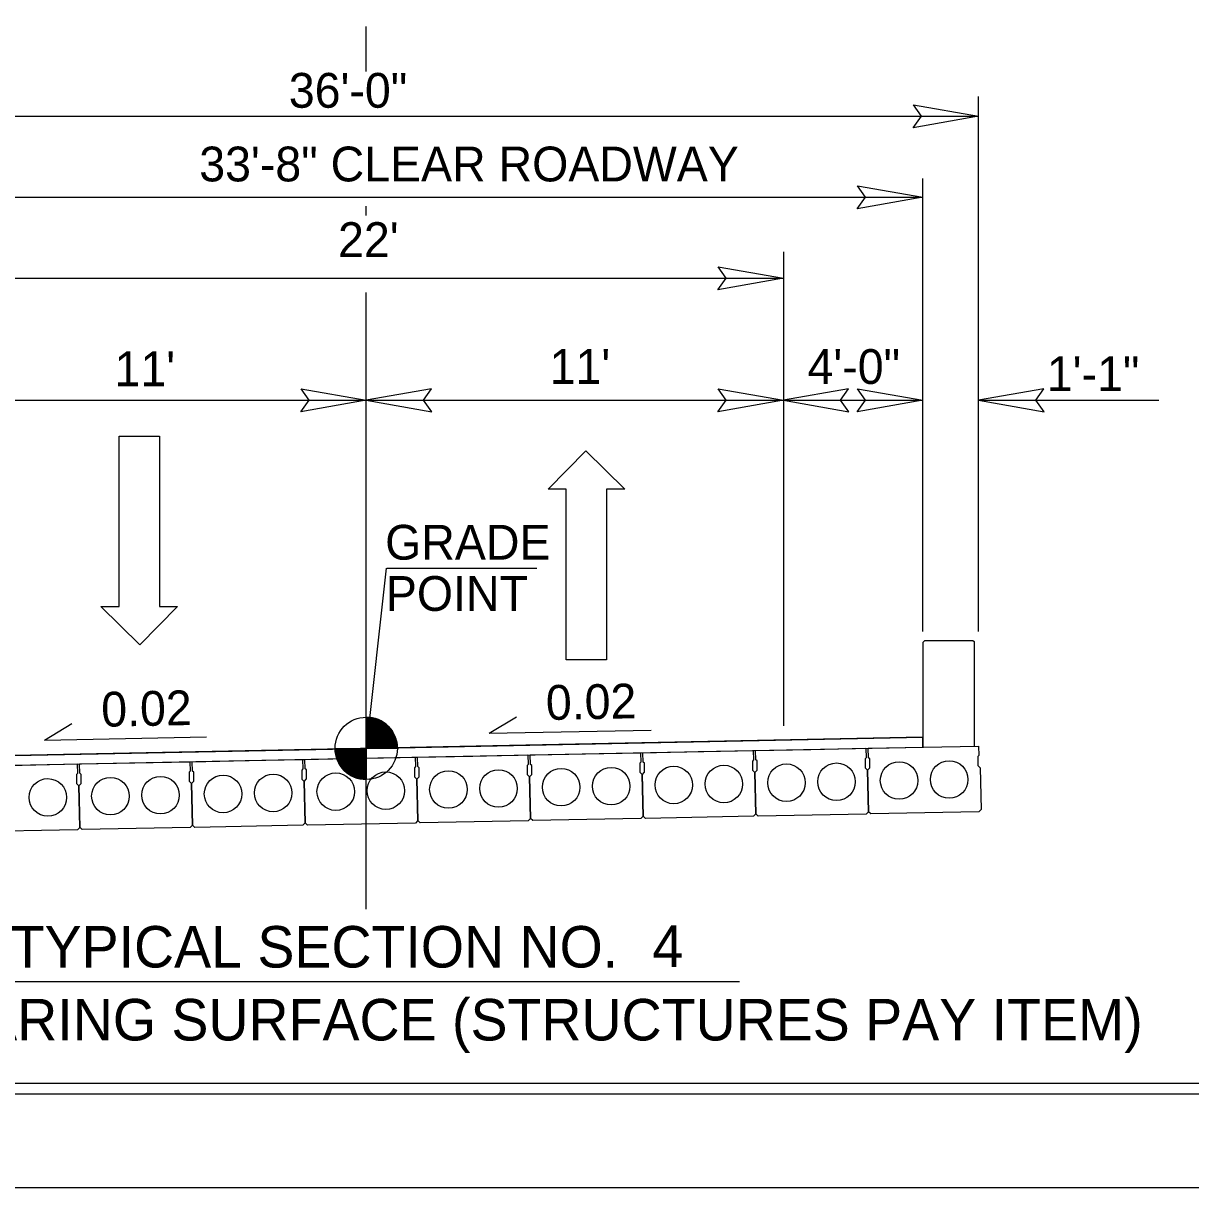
# Model space of a CAD drawing. Extents: x 573732 to 574187, y -53389 to -53257.
# Drawn here: x 573847.31 to 573880.88, y -53388.95 to -53355.48 of the extents above; entities that cross this region are included whole.
import ezdxf

# ---------------------------------------------------------------- set-up
doc = ezdxf.new("R2010")
doc.units = 0
for name, color, linetype in [('Old_Level_60', 7, 'Continuous'), ('Prop Dimension', 7, 'Continuous'), ('Prop Lane Arrow CELL', 7, 'Continuous'), ('Prop Shade Light', 7, 'Continuous'), ('Sheet Cutting Line CELL', 7, 'Continuous'), ('Sheet Plot Border Inside CELL', 7, 'Continuous'), ('Sheet Plot Border Outside CELL', 7, 'Continuous'), ('Sheet Typical CELL', 7, 'Continuous'), ('Typical Bridge Rail CELL', 7, 'Continuous'), ('Typical Grade Point Symbol CELL', 7, 'Continuous'), ('Typical Pavement Slope CELL', 7, 'Continuous'), ('Typical Pavement Slope Information CELL', 7, 'Continuous'), ('Typical Terminator CELL', 7, 'Continuous'), ('Typical Text Centerline CELL', 7, 'Continuous'), ('Typical Text Grade Point CELL', 7, 'Continuous'), ('Typical Text Label CELL', 7, 'Continuous')]:
    doc.layers.add(name, color=color, linetype=linetype)

msp = doc.modelspace()

# ---------------------------------------------------------------- linework, layer by layer
at = {"layer": 'Old_Level_60'}
for points in [[(573861.887, -53376.511), (573863.475, -53376.48), (573865.061, -53376.448), (573865.067, -53376.719), (573865.034, -53376.752), (573865.039, -53377.011), (573865.107, -53377.077), (573865.131, -53378.271), (573865.065, -53378.339), (573861.96, -53378.4), (573861.891, -53378.334), (573861.867, -53377.143), (573861.934, -53377.074), (573861.928, -53376.813), (573861.893, -53376.782), (573861.887, -53376.511)], [(573865.127, -53376.448), (573866.715, -53376.417), (573868.301, -53376.384), (573868.307, -53376.655), (573868.274, -53376.689), (573868.279, -53376.948), (573868.347, -53377.014), (573868.371, -53378.208), (573868.305, -53378.276), (573865.2, -53378.337), (573865.131, -53378.271), (573865.107, -53377.079), (573865.174, -53377.01), (573865.168, -53376.75), (573865.133, -53376.719), (573865.127, -53376.448)], [(573868.368, -53376.383), (573869.955, -53376.352), (573871.541, -53376.319), (573871.547, -53376.59), (573871.514, -53376.623), (573871.519, -53376.883), (573871.588, -53376.949), (573871.611, -53378.142), (573871.546, -53378.211), (573868.44, -53378.271), (573868.371, -53378.206), (573868.347, -53377.014), (573868.414, -53376.945), (573868.408, -53376.685), (573868.374, -53376.653), (573868.368, -53376.383)], [(573871.608, -53376.319), (573873.195, -53376.288), (573874.781, -53376.256), (573874.787, -53376.527), (573874.754, -53376.56), (573874.759, -53376.819), (573874.827, -53376.886), (573874.851, -53378.079), (573874.786, -53378.147), (573871.68, -53378.208), (573871.611, -53378.142), (573871.587, -53376.951), (573871.654, -53376.882), (573871.648, -53376.621), (573871.614, -53376.59), (573871.608, -53376.319)], [(573845.686, -53376.834), (573847.274, -53376.802), (573848.86, -53376.77), (573848.866, -53377.041), (573848.833, -53377.074), (573848.838, -53377.334), (573848.906, -53377.4), (573848.93, -53378.593), (573848.864, -53378.662), (573845.759, -53378.722), (573845.69, -53378.657), (573845.666, -53377.465), (573845.733, -53377.396), (573845.727, -53377.135), (573845.692, -53377.104), (573845.686, -53376.834)], [(573848.927, -53376.768), (573850.514, -53376.737), (573852.1, -53376.705), (573852.106, -53376.976), (573852.073, -53377.009), (573852.078, -53377.268), (573852.146, -53377.335), (573852.17, -53378.528), (573852.105, -53378.597), (573848.999, -53378.657), (573848.93, -53378.591), (573848.906, -53377.4), (573848.973, -53377.331), (573848.967, -53377.07), (573848.933, -53377.039), (573848.927, -53376.768)], [(573852.167, -53376.705), (573853.754, -53376.674), (573855.34, -53376.642), (573855.346, -53376.912), (573855.313, -53376.946), (573855.318, -53377.205), (573855.386, -53377.271), (573855.41, -53378.465), (573855.345, -53378.533), (573852.239, -53378.594), (573852.17, -53378.528), (573852.146, -53377.336), (573852.213, -53377.267), (573852.207, -53377.007), (573852.173, -53376.976), (573852.167, -53376.705)], [(573855.407, -53376.64), (573856.995, -53376.609), (573858.581, -53376.576), (573858.586, -53376.847), (573858.554, -53376.881), (573858.558, -53377.14), (573858.627, -53377.206), (573858.65, -53378.399), (573858.585, -53378.468), (573855.48, -53378.528), (573855.41, -53378.463), (573855.386, -53377.271), (573855.454, -53377.202), (573855.448, -53376.942), (573855.413, -53376.911), (573855.407, -53376.64)], [(573858.647, -53376.576), (573860.235, -53376.545), (573861.82, -53376.513), (573861.826, -53376.784), (573861.794, -53376.817), (573861.798, -53377.076), (573861.867, -53377.143), (573861.89, -53378.336), (573861.825, -53378.405), (573858.72, -53378.465), (573858.65, -53378.399), (573858.626, -53377.208), (573858.694, -53377.139), (573858.688, -53376.878), (573858.653, -53376.847), (573858.647, -53376.576)]]:
    msp.add_lwpolyline(points, dxfattribs=at)
for centre in [(573866.014, -53377.375), (573867.454, -53377.347), (573869.254, -53377.31), (573870.694, -53377.282), (573872.494, -53377.247), (573873.934, -53377.218), (573849.813, -53377.696), (573851.253, -53377.667), (573853.053, -53377.633), (573854.493, -53377.604), (573856.293, -53377.567), (573857.733, -53377.539), (573859.533, -53377.504), (573860.973, -53377.475), (573862.774, -53377.439), (573864.214, -53377.41), (573848.013, -53377.732)]:
    msp.add_ellipse(centre, major_axis=(0.001, 0.54), ratio=0.999904, dxfattribs=at)
at = {"layer": 'Prop Dimension'}
for p, q in [((573874.781, -53372.964), (573874.781, -53357.591)), ((573835.945, -53358.149), (573874.781, -53358.149)), ((573873.174, -53372.964), (573873.174, -53359.942)), ((573837.514, -53360.479), (573873.174, -53360.479)), ((573869.175, -53375.673), (573869.175, -53362.052)), ((573845.206, -53362.808), (573869.166, -53362.808)), ((573845.138, -53366.315), (573857.171, -53366.315)), ((573857.171, -53366.315), (573869.166, -53366.315)), ((573869.166, -53366.315), (573873.174, -53366.315)), ((573874.781, -53366.315), (573879.963, -53366.315)), ((573857.747, -53371.145), (573857.171, -53376.322)), ((573857.757, -53371.145), (573862.077, -53371.145))]:
    msp.add_line(p, q, dxfattribs=at)
at = {"layer": 'Prop Lane Arrow CELL'}
for p, q in [((573850.066, -53372.245), (573850.066, -53367.345)), ((573850.066, -53367.345), (573851.221, -53367.345)), ((573851.221, -53367.345), (573851.221, -53372.245)), ((573862.397, -53368.874), (573863.482, -53367.772)), ((573863.482, -53367.772), (573864.602, -53368.874)), ((573862.922, -53368.874), (573862.397, -53368.874)), ((573862.922, -53373.774), (573862.922, -53368.874)), ((573864.602, -53368.874), (573864.077, -53368.874)), ((573864.077, -53368.874), (573864.077, -53373.774)), ((573850.661, -53373.348), (573849.541, -53372.245)), ((573849.541, -53372.245), (573850.066, -53372.245)), ((573851.746, -53372.245), (573850.661, -53373.348)), ((573851.221, -53372.245), (573851.746, -53372.245)), ((573864.077, -53373.774), (573862.922, -53373.774))]:
    msp.add_line(p, q, dxfattribs=at)
at = {"layer": 'Prop Shade Light'}
for p, q in [((573873.174, -53376.002), (573857.004, -53376.325)), ((573873.174, -53376.285), (573873.174, -53376.002)), ((573857.004, -53376.325), (573837.514, -53376.715)), ((573857.01, -53376.608), (573873.174, -53376.285)), ((573837.519, -53376.998), (573857.01, -53376.608)), ((573855.34, -53376.642), (573855.407, -53376.64))]:
    msp.add_line(p, q, dxfattribs=at)
at = {"layer": 'Sheet Cutting Line CELL'}
msp.add_line((573782.222, -53388.948), (573984.302, -53388.948), dxfattribs=at)
at = {"layer": 'Sheet Plot Border Inside CELL'}
msp.add_lwpolyline([(573983.762, -53259.642), (573783.782, -53259.642), (573783.782, -53386.254), (573983.762, -53386.254)], close=True, dxfattribs=at)
at = {"layer": 'Sheet Plot Border Outside CELL'}
msp.add_lwpolyline([(573984.302, -53256.948), (573782.222, -53256.948), (573782.222, -53388.948), (573984.302, -53388.948)], close=True, dxfattribs=at)
at = {"layer": 'Sheet Typical CELL'}
msp.add_lwpolyline([(573982.262, -53259.948), (573802.262, -53259.948), (573802.262, -53385.948), (573982.262, -53385.948)], close=True, dxfattribs=at)
at = {"layer": 'Typical Bridge Rail CELL'}
for p, q in [((573873.236, -53373.221), (573873.174, -53373.284)), ((573873.174, -53373.284), (573873.174, -53376.289)), ((573873.236, -53373.221), (573874.618, -53373.221)), ((573874.618, -53373.221), (573874.651, -53373.254)), ((573874.651, -53373.254), (573874.651, -53376.258))]:
    msp.add_line(p, q, dxfattribs=at)
at = {"layer": 'Typical Grade Point Symbol CELL'}
for p, q in [((573857.171, -53376.322), (573857.171, -53375.427)), ((573856.275, -53376.322), (573857.171, -53376.322)), ((573857.169, -53377.217), (573857.171, -53376.322)), ((573857.171, -53376.322), (573857.169, -53377.217)), ((573858.066, -53376.322), (573857.171, -53376.322))]:
    msp.add_line(p, q, dxfattribs=at)
for points in [[(573857.179, -53375.427), (573857.179, -53375.427), (573857.179, -53376.322)], [(573857.196, -53375.427), (573857.196, -53376.322)], [(573857.214, -53375.429), (573857.214, -53376.322)], [(573857.232, -53375.429), (573857.232, -53376.322)], [(573857.25, -53375.431), (573857.25, -53376.322)], [(573857.268, -53375.433), (573857.268, -53376.322)], [(573857.286, -53375.435), (573857.286, -53376.322)], [(573857.304, -53375.437), (573857.304, -53376.322)], [(573857.322, -53375.439), (573857.322, -53376.322)], [(573857.34, -53375.443), (573857.34, -53376.322)], [(573857.358, -53375.447), (573857.358, -53376.322)], [(573857.376, -53375.451), (573857.376, -53376.322)], [(573857.393, -53375.455), (573857.393, -53376.322)], [(573857.411, -53375.46), (573857.411, -53376.322)], [(573857.429, -53375.465), (573857.429, -53376.322)], [(573857.447, -53375.47), (573857.447, -53376.322)], [(573857.465, -53375.476), (573857.465, -53376.322)], [(573857.483, -53375.482), (573857.483, -53376.322)], [(573857.501, -53375.49), (573857.501, -53376.322)], [(573857.519, -53375.498), (573857.519, -53376.322)], [(573857.537, -53375.506), (573857.537, -53376.322)], [(573857.555, -53375.514), (573857.555, -53376.322)], [(573857.572, -53375.522), (573857.572, -53376.322)], [(573857.59, -53375.532), (573857.59, -53376.322)], [(573857.608, -53375.542), (573857.608, -53376.322)], [(573857.626, -53375.552), (573857.626, -53376.322)], [(573857.644, -53375.562), (573857.644, -53376.322)], [(573857.662, -53375.574), (573857.662, -53376.322)], [(573857.68, -53375.586), (573857.68, -53376.322)], [(573857.698, -53375.6), (573857.698, -53376.322)], [(573857.716, -53375.612), (573857.716, -53376.322)], [(573857.734, -53375.626), (573857.734, -53376.322)], [(573857.751, -53375.641), (573857.751, -53376.322)], [(573857.769, -53375.657), (573857.769, -53376.322)], [(573857.787, -53375.673), (573857.787, -53376.322)], [(573857.805, -53375.691), (573857.805, -53376.322)], [(573857.823, -53375.709), (573857.823, -53376.322)], [(573857.841, -53375.729), (573857.841, -53376.322)], [(573857.859, -53375.751), (573857.859, -53376.322)], [(573857.877, -53375.773), (573857.877, -53376.322)], [(573857.895, -53375.797), (573857.895, -53376.322)], [(573857.913, -53375.823), (573857.913, -53376.322)], [(573857.931, -53375.85), (573857.931, -53376.322)], [(573857.948, -53375.88), (573857.948, -53376.322)], [(573857.966, -53375.912), (573857.966, -53376.322)], [(573857.984, -53375.95), (573857.984, -53376.322)], [(573858.002, -53375.992), (573858.002, -53376.322)], [(573858.02, -53376.041), (573858.02, -53376.322)], [(573858.038, -53376.103), (573858.038, -53376.322)], [(573856.279, -53376.322), (573856.279, -53376.419)], [(573856.297, -53376.322), (573856.297, -53376.525)], [(573856.315, -53376.322), (573856.315, -53376.588)], [(573856.333, -53376.322), (573856.333, -53376.642)], [(573856.351, -53376.322), (573856.351, -53376.684)], [(573856.369, -53376.322), (573856.369, -53376.722)], [(573856.387, -53376.322), (573856.387, -53376.755)], [(573856.405, -53376.322), (573856.405, -53376.787)], [(573856.423, -53376.322), (573856.423, -53376.815)], [(573856.441, -53376.322), (573856.441, -53376.841)], [(573856.458, -53376.322), (573856.458, -53376.865)], [(573856.476, -53376.322), (573856.476, -53376.887)], [(573856.494, -53376.322), (573856.494, -53376.909)], [(573856.512, -53376.322), (573856.512, -53376.929)], [(573856.53, -53376.322), (573856.53, -53376.948)], [(573856.548, -53376.322), (573856.548, -53376.966)], [(573856.566, -53376.322), (573856.566, -53376.982)], [(573856.584, -53376.322), (573856.584, -53376.998)], [(573856.602, -53376.322), (573856.602, -53377.014)], [(573856.62, -53376.322), (573856.62, -53377.028)], [(573856.638, -53376.322), (573856.638, -53377.042)], [(573856.655, -53376.322), (573856.655, -53377.054)], [(573856.673, -53376.322), (573856.673, -53377.066)], [(573856.691, -53376.322), (573856.691, -53377.078)], [(573856.709, -53376.322), (573856.709, -53377.09)], [(573856.727, -53376.322), (573856.727, -53377.1)], [(573856.745, -53376.322), (573856.745, -53377.11)], [(573856.763, -53376.322), (573856.763, -53377.12)], [(573856.781, -53376.322), (573856.781, -53377.128)], [(573856.799, -53376.322), (573856.799, -53377.136)], [(573856.817, -53376.322), (573856.817, -53377.143)], [(573856.834, -53376.322), (573856.834, -53377.151)], [(573856.852, -53376.322), (573856.852, -53377.159)], [(573856.87, -53376.322), (573856.87, -53377.165)], [(573856.888, -53376.322), (573856.888, -53377.171)], [(573856.906, -53376.322), (573856.906, -53377.177)], [(573856.924, -53376.322), (573856.924, -53377.181)], [(573856.942, -53376.322), (573856.942, -53377.187)], [(573856.96, -53376.322), (573856.96, -53377.191)], [(573856.978, -53376.322), (573856.978, -53377.195)], [(573856.996, -53376.322), (573856.996, -53377.199)], [(573857.013, -53376.322), (573857.013, -53377.203)], [(573857.031, -53376.322), (573857.031, -53377.205)], [(573857.049, -53376.322), (573857.049, -53377.209)], [(573857.067, -53376.322), (573857.067, -53377.211)], [(573857.085, -53376.322), (573857.085, -53377.213)], [(573857.103, -53376.322), (573857.103, -53377.215)], [(573857.121, -53376.322), (573857.121, -53377.215)], [(573857.139, -53376.322), (573857.139, -53377.217)], [(573857.157, -53376.322), (573857.157, -53377.217), (573857.157, -53377.217)], [(573858.056, -53376.195), (573858.056, -53376.322)]]:
    msp.add_lwpolyline(points, dxfattribs=at)
msp.add_circle((573857.17, -53376.322), 0.895, dxfattribs=at)
for start, end in [(359.9905, 89.9905), (179.9905, 269.9905)]:
    msp.add_arc((573857.17, -53376.322), 0.895, start, end, dxfattribs=at)
at = {"layer": 'Typical Pavement Slope CELL'}
for p, q in [((573857.171, -53376.322), (573873.174, -53376.002)), ((573873.174, -53376.002), (573873.174, -53376.285)), ((573837.514, -53376.715), (573857.171, -53376.322)), ((573857.176, -53376.605), (573873.174, -53376.285)), ((573837.514, -53376.995), (573857.176, -53376.605))]:
    msp.add_line(p, q, dxfattribs=at)
at = {"layer": 'Typical Pavement Slope Information CELL'}
for p, q in [((573860.704, -53375.89), (573861.487, -53375.417)), ((573847.917, -53376.085), (573848.7, -53375.612)), ((573860.704, -53375.89), (573865.364, -53375.797)), ((573847.917, -53376.085), (573852.578, -53375.992))]:
    msp.add_line(p, q, dxfattribs=at)
at = {"layer": 'Typical Terminator CELL'}
for points in [[(573872.906, -53357.827), (573874.781, -53358.149), (573872.896, -53358.483), (573873.136, -53358.149)], [(573871.299, -53360.156), (573873.174, -53360.479), (573871.288, -53360.812), (573871.528, -53360.479)], [(573867.292, -53362.485), (573869.166, -53362.808), (573867.281, -53363.141), (573867.521, -53362.808)], [(573855.296, -53365.992), (573857.171, -53366.315), (573855.285, -53366.648), (573855.525, -53366.315)], [(573859.045, -53365.992), (573857.171, -53366.315), (573859.056, -53366.648), (573858.816, -53366.315)], [(573867.292, -53365.992), (573869.166, -53366.315), (573867.281, -53366.648), (573867.521, -53366.315)], [(573871.041, -53365.992), (573869.166, -53366.315), (573871.051, -53366.648), (573870.812, -53366.315)], [(573871.299, -53365.992), (573873.174, -53366.315), (573871.288, -53366.648), (573871.528, -53366.315)], [(573876.656, -53365.992), (573874.781, -53366.315), (573876.666, -53366.648), (573876.427, -53366.315)]]:
    msp.add_lwpolyline(points, close=True, dxfattribs=at)
at = {"layer": 'Typical Text Centerline CELL'}
for p, q in [((573857.171, -53356.866), (573857.171, -53355.571)), ((573857.171, -53361.006), (573857.171, -53360.742)), ((573857.171, -53380.943), (573857.171, -53363.221))]:
    msp.add_line(p, q, dxfattribs=at)
at = {"layer": 'Typical Text Label CELL'}
msp.add_line((573846.304, -53383.022), (573867.908, -53383.022), dxfattribs=at)

# ---------------------------------------------------------------- texts
at = {"layer": 'Typical Pavement Slope Information CELL'}
for s, rotation, p in [('36\'-0"', 360, (573854.943, -53357.91)), ("22'", 360, (573856.359, -53362.2)), ("11'", 360, (573849.93, -53365.914)), ("11'", 360, (573862.444, -53365.846)), ('4\'-0"', 360, (573869.86, -53365.848)), ('0.02', 1.1457, (573862.345, -53375.508)), ('0.02', 1.1457, (573849.558, -53375.703))]:
    msp.add_text(s, height=1, rotation=rotation, dxfattribs=at).set_placement(p)
for s, p in [('33\'-8" CLEAR ROADWAY', (573852.367, -53360.027)), ('1\'-1"', (573876.742, -53366.055))]:
    msp.add_text(s, height=1, dxfattribs=at).set_placement(p)
at = {"layer": 'Typical Text Grade Point CELL'}
for s, p in [('GRADE', (573857.713, -53370.899)), ('POINT', (573857.734, -53372.371))]:
    msp.add_text(s, height=1, dxfattribs=at).set_placement(p)
at = {"layer": 'Typical Text Label CELL'}
for s, height, p in [('TYPICAL SECTION NO.  ', 1.19356, (573846.944, -53382.622)), ('4', 1.194, (573865.397, -53382.606))]:
    msp.add_text(s, height=height, rotation=360, dxfattribs=at).set_placement(p)
msp.add_text('CONCRETE WEARING SURFACE (STRUCTURES PAY ITEM)', height=1.19356, dxfattribs=at).set_placement((573834.098, -53384.718))

doc.saveas('drawing.dxf')
